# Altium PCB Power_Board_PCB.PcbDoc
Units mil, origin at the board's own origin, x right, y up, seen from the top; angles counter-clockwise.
Board outline 4240 x 2630 mil, 2 copper layers (Top Layer, Bottom Layer); 28 components, 19 nets, 62 pads, 0 vias.
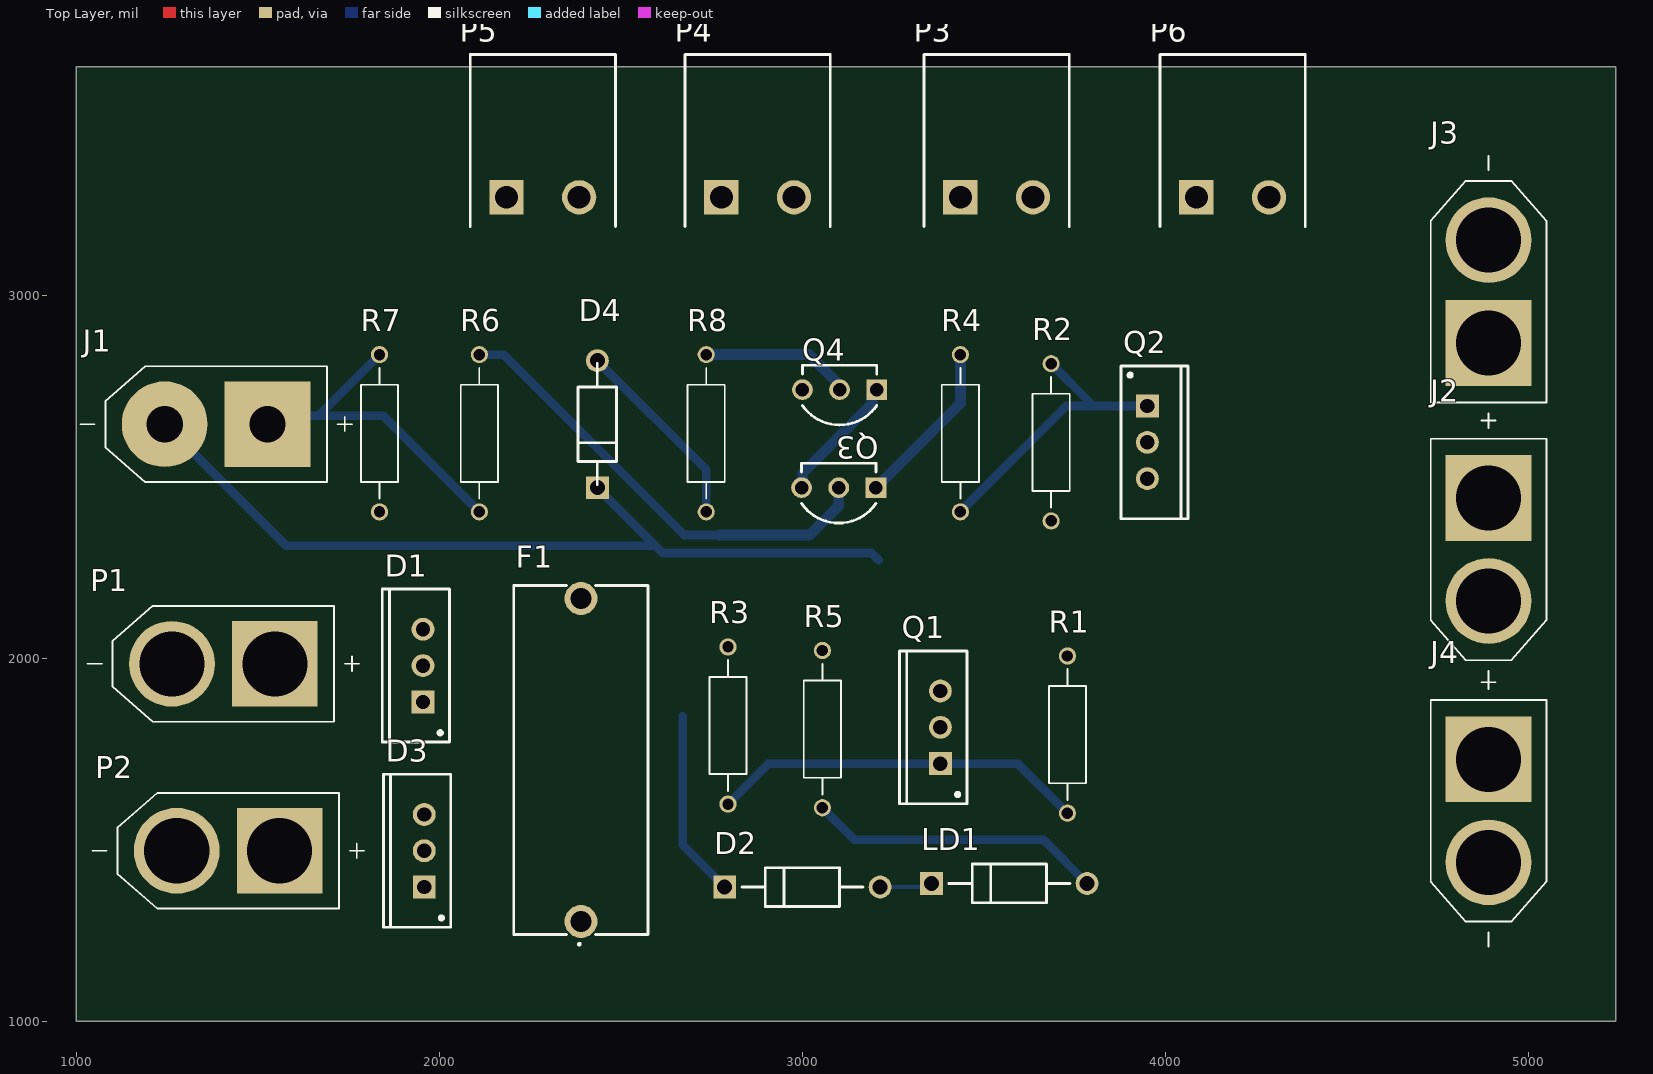
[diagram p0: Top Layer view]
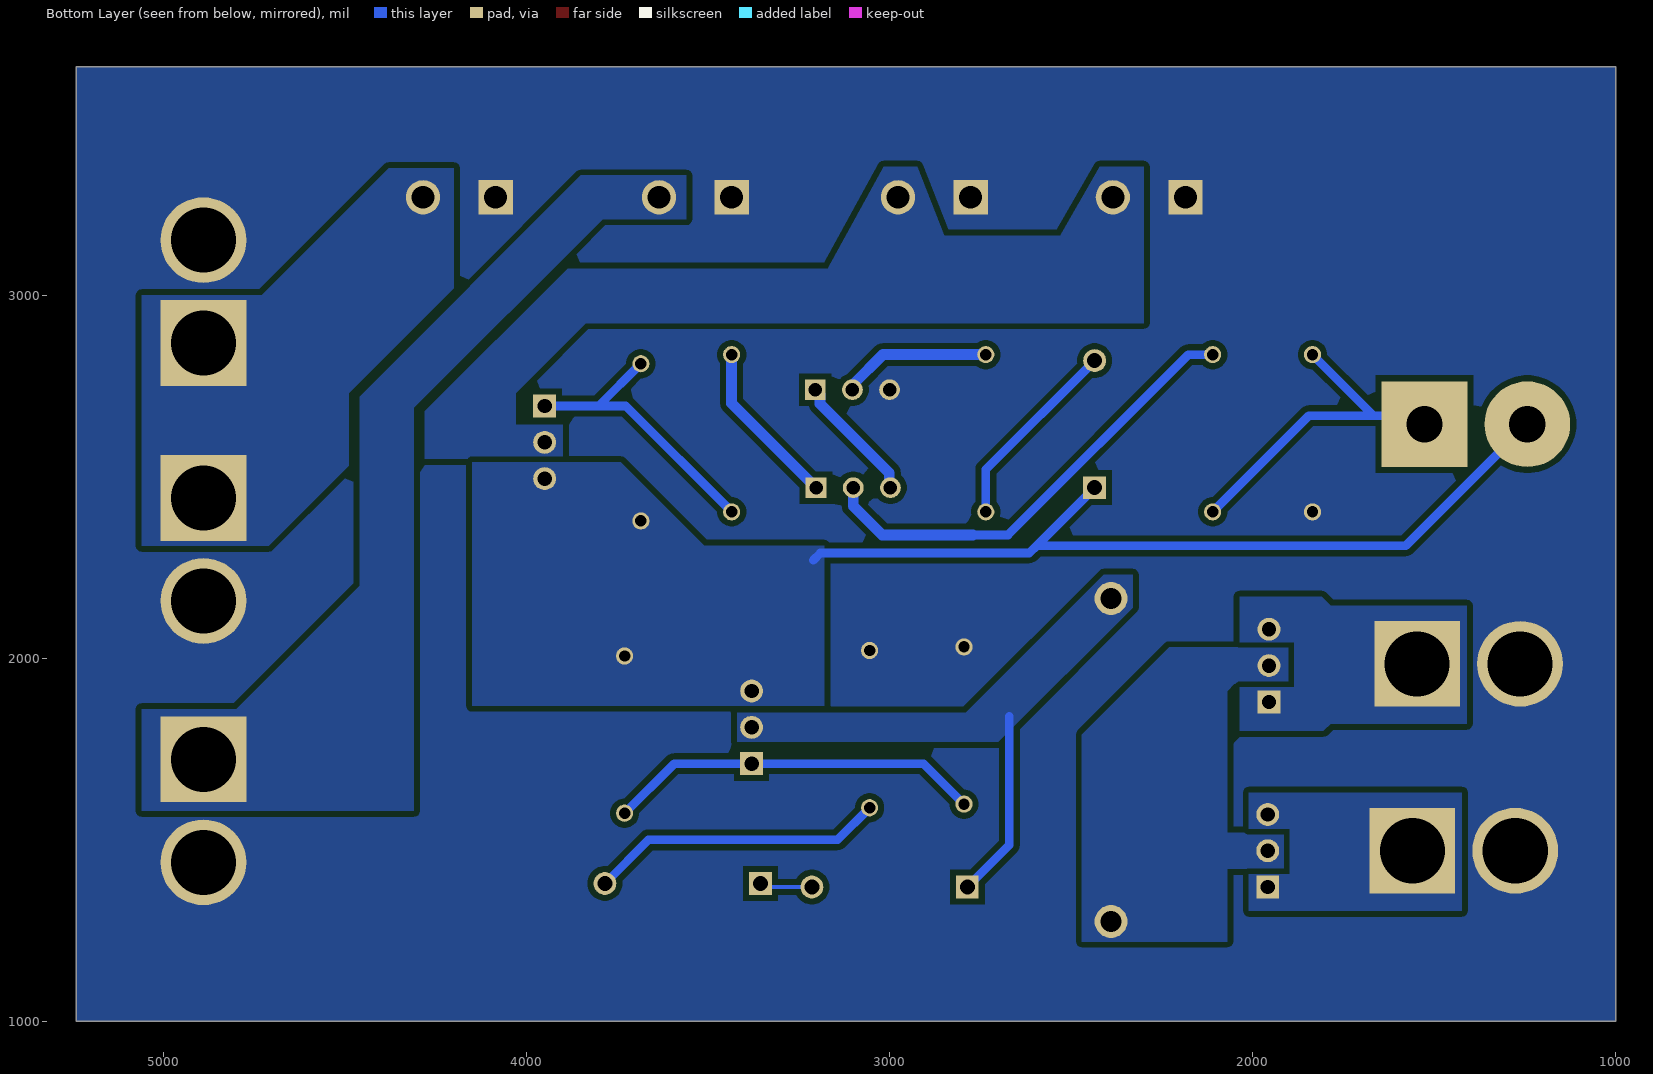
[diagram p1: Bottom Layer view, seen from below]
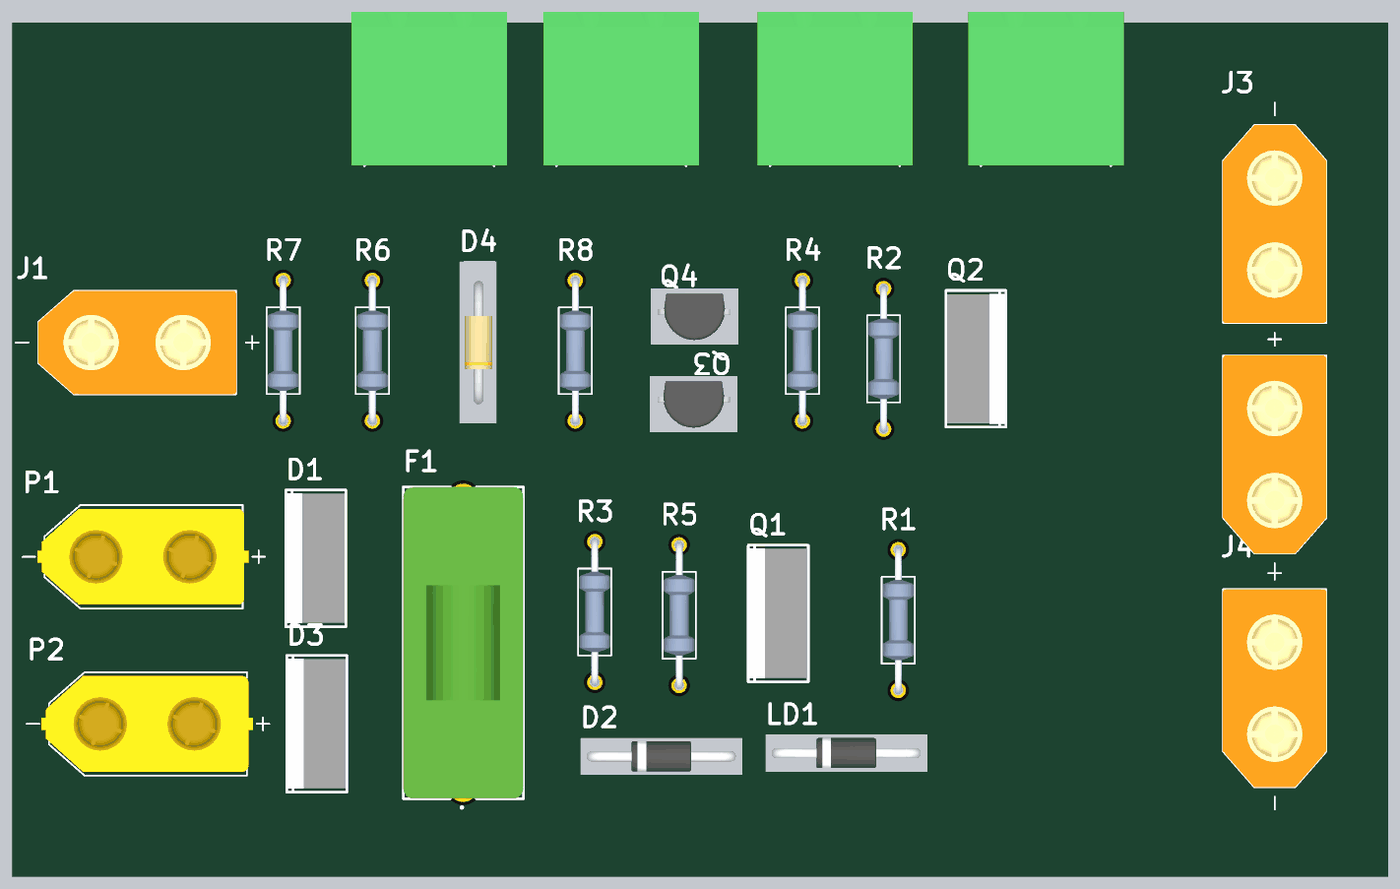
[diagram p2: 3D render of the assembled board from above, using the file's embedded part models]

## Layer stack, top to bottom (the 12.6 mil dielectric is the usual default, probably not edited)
Top Solder: solder mask 0.4, Solder Resist, Dk 3.5
Top Layer: signal copper 1.4
Dielectric 1: dielectric 12.6, FR-4, Dk 4.8
Bottom Layer: signal copper 1.4
Bottom Solder: solder mask 0.4, Solder Resist, Dk 3.5

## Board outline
1000,1000 1000,3630 5240,3630 5240,1000

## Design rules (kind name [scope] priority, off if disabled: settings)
Clearance [All] p1: gap=16 ignorepadtopadclearanceinfootprint=FALSE
HoleSize [All] p1: absolutevalues=TRUE maxlimit=500 minlimit=14 maxpercent=80.000 minpercent=20.000
PlaneConnect [All] p1: planeconnectstyle=Direct reliefexpansion=20 reliefentries=4 reliefconductorwidth=10 reliefairgap=10
PolygonConnect [All] p1: connectstyle=Direct reliefconductorwidth=10 reliefentries=4 polygonreliefangle="90 Angle" airgapwidth=10
RoutingVias [All] p1: holewidth=28 width=50 viastyle="Through Hole" minholewidth=28 minwidth=50 maxholewidth=28 maxwidth=50
SilkToSilkClearance [All] p1: silktosilkclearance=1
SilkToSolderMaskClearance [IsPad] p1: minsilkscreentomaskgap=5 clearancetoexposedcopper=TRUE
SolderMaskExpansion [All] p1: expansion=10 istentingtop=FALSE
SupplyNets "Schematic Supply Nets_6" [InNet('+BAT_INV_PROT')] p1: voltage=0.000
SupplyNets "Schematic Supply Nets_5" [InNet('+5V_JETSON/LED')] p2: voltage=0.000
SupplyNets "Schematic Supply Nets_4" [InNet('+BAT_SAFE')] p3: voltage=0.000
SupplyNets "Schematic Supply Nets_3" [InNet('+24V_BASE/MANIP')] p4: voltage=0.000
SupplyNets "Schematic Supply Nets" [InNet('GND')] p5: voltage=0.000
UnRoutedNet [All] p1: checkbadconnections=TRUE
Width [All] p1: maxlimit=100 minlimit=24 preferedwidth=30 minimp=50.000000 maximp=50.000000 favimp=50.000000
25 further rules are at their usual default settings.

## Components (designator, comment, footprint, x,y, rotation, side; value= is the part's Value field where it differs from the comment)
D1 "STPS10H100CT" TO-220AB 1955,1980 r90 top
D2 "1N4004" DO41 3000,1370 r180 top
D3 "STPS10H100CT" TO-220AB 1958.27,1470 r90 top
D4 "Zener PTH - Gen." "DO41 - Zener" 2435,2645 r270 top value=18V
F1 "Fuse Holder 20x5" "FUSE HOLDER 20x5" 2390,1720 r90 top
J1 "XT60-M-180" AMASS_XT60-M#1 1385,2645 r180 top
J2 "XT60-M-180" AMASS_XT60-M#2 4890,2300 r270 top
J3 "XT60-M-180" AMASS_XT60-M#2 4890,3010 r90 top
J4 "XT60-M-180" AMASS_XT60-M#2 4890,1580 r270 top
LD1 "LED PTH - Gen." DO41 3570,1380 r180 top
P1 "CON XT60 - Male" "CON XT60 MALE" 1405,1985 r180 top
P2 "CON XT60 - Male" "CON XT60 MALE" 1418.27,1470 r180 top
P3 "CON KF2 EDGRC-5.08-02P" "BORNE 5.08 RA 2P" 3435,3270 r180 top
P4 "CON KF2 EDGRC-5.08-02P" "BORNE 5.08 RA 2P" 2776.67,3270 r180 top
P5 "CON KF2 EDGRC-5.08-02P" "BORNE 5.08 RA 2P" 2185,3270 r180 top
P6 "CON KF2 EDGRC-5.08-02P" "BORNE 5.08 RA 2P" 4085,3270 r180 top
Q1 "IRF9540N" TO-220AB 3380,1810 r90 top
Q2 "IRF9540N" TO-220AB 3950,2595 r270 top
Q3 "BC548" "TO-92 LPM" 3100,2455.04 r270 top
Q4 "BC548" "TO-92 LPM" 3102.36,2725.04 r270 top
R1 "10K" "RES PTH" 3730,1790 r270 top
R2 "10K" "RES PTH" 3685,2595 r270 top
R3 "20K" "RES PTH" 2795,1815 r90 top
R4 "20K" "RES PTH" 3435,2620 r90 top
R5 "20K" "RES PTH" 3055,1805 r270 top
R6 "10K" "RES PTH" 2110,2620 r270 top
R7 "50K" "RES PTH" 1835,2620 r270 top
R8 "50K" "RES PTH" 2735,2620 r270 top

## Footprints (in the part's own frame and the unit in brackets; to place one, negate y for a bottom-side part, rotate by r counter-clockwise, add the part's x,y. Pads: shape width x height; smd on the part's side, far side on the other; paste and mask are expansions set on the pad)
AMASS_XT60-M#1 [mm]
  round 6 hole 2.54: N(3.6,0)
  rect 6x6 / inner round 6 / far side rect 6x6 hole 2.54: P(-3.6,0)
  silkscreen extent -9.5,-4.05 9.5,4.05, body extent -7.75,-4.05 7.75,4.05, height 16
AMASS_XT60-M#2 [mm]
  round 6 hole 4.55: N(3.6,0)
  rect 6x6 / inner round 6 / far side rect 6x6 hole 4.55: P(-3.6,0)
  silkscreen extent -9.5,-4.05 9.5,4.05, body extent -7.75,-4.05 7.75,4.05, height 16
"BORNE 5.08 RA 2P" [mm] "Terminal block 5.08mm right angle 2 ways"
  rect 2.4x2.4 hole 1.6: 1(0,0)
  round 2.4 hole 1.6: 2(-5.08,0)
  silkscreen extent -7.62,-10 2.54,2.03, body extent -8.63,-9.99 3.53,2.01, height 8.53
"CON XT60 MALE" [mm]
  round 6 hole 4.55: N(3.6,0)
  rect 6x6 / inner round 6 / far side rect 6x6 hole 4.55: P(-3.6,0)
  silkscreen extent -9.5,-4.05 9.5,4.05, body extent -8.22,-3.75 8.33,3.75, height 16.13
DO41 [mm]
  rect 1.6x1.6 hole 1.05 paste-2539.97 mask+0: 1(5.438,0)
  round 1.6 hole 1.05 paste-2539.97 mask+0: 2(-5.438,0)
  silkscreen extent -4.24,-1.35 4.24,1.35, body extent -6.34,-1.45 6.34,1.45, height 0.25
"DO41 - Zener" [mm]
  rect 1.6x1.6 hole 1.05 paste-2539.97 mask+0: 1(4.445,0)
  round 1.6 hole 1.05 paste-2539.97 mask+0: 2(-4.445,0)
  silkscreen extent -4.24,-1.35 4.24,1.35, body extent -4.82,-1.02 4.82,1.12, height 2.15
"FUSE HOLDER 20x5" [mm]
  round 2.3 hole 1.5: 1(-11.3,0) 2(11.3,0)
  silkscreen extent -12.95,-4.7 12.2,4.7, body extent -12.2,-4.7 12.2,4.7, height 13.36
"RES PTH" [mm]
  round 1.2 hole 0.8: 1(-5.5,0) 2(5.5,0)
  silkscreen extent -4.58,-1.3 4.58,1.3, body extent -5.77,-1.2 5.77,1.2, height 2.4
"TO-92 LPM" [mm] "Pin 1 is the leftmost pin when looking at the flat side."
  rect 1.45x1.45 hole 0.95 paste-2539.97 mask+0: 1(-0.38,2.6)
  round 1.45 hole 0.95 paste-2539.97 mask+0: 2(-0.38,0) 3(-0.38,-2.6)
  silkscreen extent -2.09,-2.6 2.09,2.6, body extent -2.19,-3.42 2.19,3.42, height 0.25
TO-220AB [mm] "TO, Thru-Hole, Vertical, Heatsink Mounted; 3 In-Line Leads; Pitch 2.54 mm"
  rect 1.6x1.6 hole 1: 1(-2.54,0)
  round 1.6 hole 1: 2(0,0) 3(2.54,0)
  silkscreen extent -5.35,-1.85 5.35,2.85, body extent -5.06,-1.76 5.1,2.81, height 18.54

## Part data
D1 D3: "Diodo Schottky de 2x5A e 100V de corrente reversa"
D2: "DIODE - PTH 400V 1A"
D4: "DIODE - PTH Zener generic"
J1 J2 J3 J4: library part CMP-004-000000-5, "Plug; DC supply; XT60; male; PIN: 2; for cable; soldered; 30A; 500V", Package=Package
LD1: "Generic PTH Led"
P3 P4 P5 P6: "CONECTOR - Borne 2 Vias Macho Passo 5.08mm 90º KF2 EDGRC-5.08-02P Fechado."
Q1 Q2: "Mosfet PMOS PTH - 23A Id"
Q3 Q4: "TRANSISTOR -  TBJ NPN"
R1 R2 R3 R4 R5 R6 R7 R8: library part "RES PTH - Gen.", "Generic PTH resistor for general purpose"

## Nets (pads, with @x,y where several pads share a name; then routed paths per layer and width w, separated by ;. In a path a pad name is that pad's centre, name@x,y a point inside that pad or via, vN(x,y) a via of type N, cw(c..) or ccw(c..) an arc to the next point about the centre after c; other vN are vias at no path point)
+5V_JETSON/LED: J4.P P3.2
+24V_BASE/MANIP: J2.P J3.P P6.2
+BAT_INV_PROT: D4.1 J1.N Q1.3 Q2.3 R1.1 R2.2 | length 2348.3
  Bottom Layer w24: J1.N 1578.27,2310 2595,2310 ; D4.1 2595,2310 ; 3210,2270 3190,2290 2615,2290 2595,2310
+BAT_SAFE: P4.2 P5.2 Q2.2
GND: J2.N J3.N J4.N P1.N P2.N P3.1 P4.1 P5.1 P6.1 Q4.3 R3.2 R5.1 R7.2
NetD1_1: D1.1 D1.3 P1.P
NetD1_2: D1.2 D3.2 F1.1
NetD2_1: D2.1 F1.2 Q1.2 | length 518
  Bottom Layer w24: 2670,1840 2670,1485.91 D2.1
NetD2_2: D2.2 LD1.1 | length 126
  Bottom Layer w10: D2.2@3234.09,1370 3345.91,1370 LD1.1
NetD3_1: D3.1 D3.3 P2.P
NetD4_2: D4.2 R8.2 | length 540.8
  Bottom Layer w24: D4.2 2735,2520 R8.2
NetJ1_P: J1.P R6.2 R7.1 | length 940.5
  Bottom Layer w24: J1.P 1550.05,2668.32 1666.78,2668.32 ; R7.1 1666.78,2668.32 ; R6.2 1845.15,2668.32 1666.78,2668.32
NetLD1_2: LD1.2 R5.2 | length 815.4
  Bottom Layer w24: R5.2 3143.46,1500 3664.09,1500 LD1.2
NetQ1_1: Q1.1 R1.2 R3.1 | length 1037.8
  Bottom Layer w24: R3.1 2906.54,1710 Q1.1 3593.46,1710 R1.2
NetQ2_1: Q2.1 R2.1 R4.1 | length 800.6
  Bottom Layer w24: R4.1 3726.54,2695 3801.54,2695 ; R2.1 3801.54,2695 ; Q2.1 3801.54,2695
NetQ3_1: Q3.1 R4.2 | length 462.9
  Bottom Layer w30: Q3.1 3435,2702.64 R4.2
NetQ3_2: Q3.2 R6.1 | length 1278.8
  Bottom Layer w24: R6.1 2177.52,2836.54 2674.06,2340 2770.95,2340
  Bottom Layer w30: 2770.95,2340 3020,2340 3100,2420 Q3.2
NetQ3_3: Q3.3 Q4.1 | length 355.8
  Bottom Layer w30: Q3.3 3000.82,2473.18 3000.82,2510.82 3191.18,2701.18 3191.18,2726.46 Q4.1
NetQ4_2: Q4.2 R8.1 | length 398.8
  Bottom Layer w30: R8.1 3018.5,2836.54 Q4.2@3100,2755.04

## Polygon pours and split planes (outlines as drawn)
GND on Bottom Layer "NONET_L-01_P-001" (solid, pour order 14): 1000,1000 5240,1000 5240,3630 1000,3630
+BAT_INV_PROT on Bottom Layer "NONET_L-01_P-001" (solid, pour order 8): 3180,1870 3180,2310 3510,2310 3740,2540 4150,2540 4150,1870
+24V_BASE/MANIP on Bottom Layer "NONET_L-01_P-001" (solid, pour order 13): 4200,3350 4380,3350 4730,3000 5060,3000 5060,2310 4710,2310 4490,2530 4490,2730 4200,3020
+5V_JETSON/LED on Bottom Layer "NONET_L-01_P-001" (solid, pour order 11): 3560,3330 3560,3210 3790,3210 4310,2690 4310,1580 5060,1580 5060,1860 4800,1860 4460,2200 4460,2720 3850,3330
NetD2_1 on Bottom Layer "NONET_L-01_P-001" (solid, pour order 7): 2330,2230 2330,2140 2700,1770 3420,1770 3420,1850 2790,1850 2410,2230
+BAT_SAFE on Bottom Layer "NONET_L-01_P-001" (solid, pour order 9): 3900,2550 3900,2643.69 4030,2643.69 4030,2730 3836.31,2923.69 2300,2923.69 2300,3353.69 2420.8,3353.69 2530,3163.69 2850,3163.69 2923.69,3353.69 3016.31,3353.69 3170,3073.08 3886.92,3073.08 4280,2680 4280,2550
NetD3_1 on Bottom Layer "NONET_L-01_P-001" (solid, pour order 3): 1423.27,1630 1423.27,1305 1798.27,1305 2010,1305 2010,1405 1898.27,1405 1898.27,1530 2010,1530 2010,1630 1798.27,1630
NetD1_2 on Bottom Layer "NONET_L-01_P-001" (solid, pour order 5): 1900,2030 1900,1930 2050,1930 2070,1910 2070,1520 1910,1520 1910,1420 2070,1420 2070,1220 2470,1220 2470,1790 2230,2030
NetD1_1 on Bottom Layer "NONET_L-01_P-001" (solid, pour order 2): 1410,2145 1410,1820 1785,1820 1805,1800 2035,1800 2035,1920 1885,1920 1885,2045 2035,2045 2035,2170 1810,2170 1785,2145

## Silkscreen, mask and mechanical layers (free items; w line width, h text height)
Mechanical 1:
  the board outline again, w10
